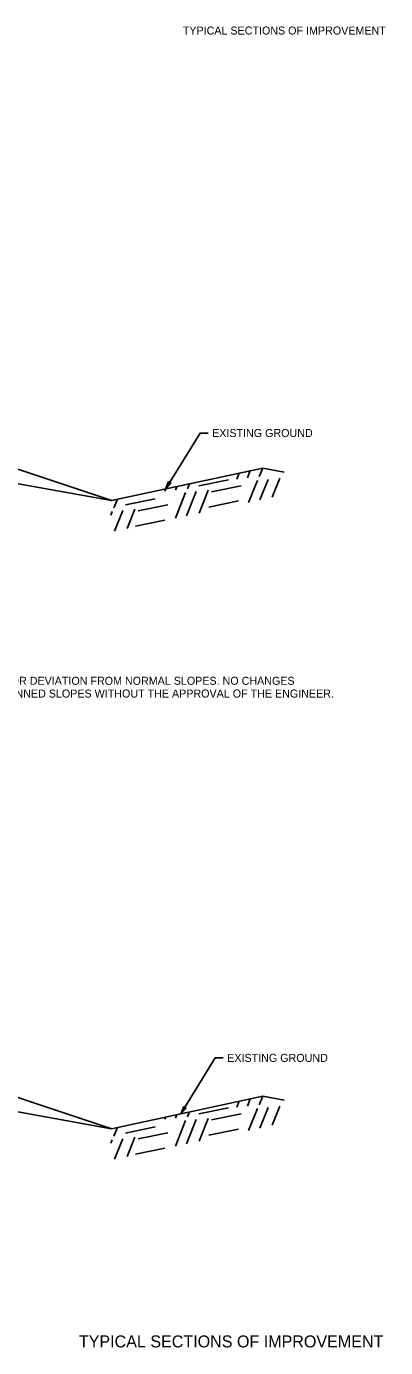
# Model space of a CAD drawing. Extents: x 1734743 to 1735935, y 759845 to 763831.
# Drawn here: x 1735803.1 to 1735830, y 759845.2 to 759944.2 of the extents above; entities that cross this region are included whole.
import ezdxf

# ---------------------------------------------------------------- set-up
doc = ezdxf.new("R2010")
doc.units = 0
for name, color, linetype in [('1', 7, 'Continuous'), ('10', 7, 'Continuous'), ('19', 7, 'Continuous'), ('20', 7, 'Continuous'), ('G-ANNO-TEXT', 7, 'Continuous')]:
    doc.layers.add(name, color=color, linetype=linetype)

msp = doc.modelspace()

# ---------------------------------------------------------------- linework, layer by layer
at = {"layer": '19'}
for p, q in [((1735809.505, 759908.711), (1735795.046, 759913.532)), ((1735820.551, 759910.501), (1735820.81, 759911.149)), ((1735816.033, 759909.813), (1735818.244, 759910.268)), ((1735818.863, 759910.323), (1735819.036, 759910.769)), ((1735819.661, 759910.409), (1735819.878, 759910.951)), ((1735819.757, 759908.573), (1735820.413, 759910.221)), ((1735820.6, 759908.755), (1735821.214, 759910.298)), ((1735821.529, 759908.963), (1735822.101, 759910.399)), ((1735813.483, 759909.415), (1735813.547, 759909.59)), ((1735814.268, 759907.394), (1735815.033, 759909.314)), ((1735814.283, 759909.491), (1735814.389, 759909.772)), ((1735815.111, 759907.576), (1735815.833, 759909.39)), ((1735815.17, 759909.593), (1735815.321, 759909.97)), ((1735816.042, 759907.774), (1735816.723, 759909.482)), ((1735816.975, 759909.368), (1735819.195, 759909.826)), ((1735809.671, 759908.162), (1735809.931, 759908.81)), ((1735810.534, 759908.381), (1735812.755, 759908.839)), ((1735811.485, 759907.939), (1735813.696, 759908.394)), ((1735816.766, 759908.224), (1735818.986, 759908.682)), ((1735809.442, 759907.626), (1735809.543, 759907.885)), ((1735809.72, 759906.416), (1735810.344, 759907.961)), ((1735810.652, 759906.614), (1735811.231, 759908.063)), ((1735811.276, 759906.795), (1735813.487, 759907.25)), ((1735809.505, 759861.629), (1735795.046, 759866.45)), ((1735818.863, 759863.24), (1735819.036, 759863.686)), ((1735819.661, 759863.326), (1735819.878, 759863.869)), ((1735820.551, 759863.418), (1735820.81, 759864.066)), ((1735814.283, 759862.409), (1735814.389, 759862.69)), ((1735815.17, 759862.511), (1735815.321, 759862.888)), ((1735816.033, 759862.73), (1735818.244, 759863.185)), ((1735816.975, 759862.285), (1735819.195, 759862.743)), ((1735819.757, 759861.49), (1735820.413, 759863.139)), ((1735820.6, 759861.673), (1735821.214, 759863.215)), ((1735821.529, 759861.88), (1735822.101, 759863.317)), ((1735809.671, 759861.079), (1735809.931, 759861.727)), ((1735810.534, 759861.299), (1735812.755, 759861.757)), ((1735813.483, 759862.333), (1735813.547, 759862.507)), ((1735814.268, 759860.311), (1735815.033, 759862.231)), ((1735815.111, 759860.494), (1735815.833, 759862.308)), ((1735816.042, 759860.692), (1735816.723, 759862.4)), ((1735809.442, 759860.544), (1735809.543, 759860.802)), ((1735809.72, 759859.333), (1735810.344, 759860.879)), ((1735810.652, 759859.531), (1735811.231, 759860.98)), ((1735811.485, 759860.857), (1735813.696, 759861.312)), ((1735816.766, 759861.142), (1735818.986, 759861.599)), ((1735811.276, 759859.713), (1735813.487, 759860.168))]:
    msp.add_line(p, q, dxfattribs=at)
for points in [[(1735737.574, 759909.405), (1735737.825, 759909.397), (1735746.995, 759910.076), (1735752.775, 759907.356), (1735767.375, 759908.375), (1735787.755, 759909.053), (1735799.985, 759910.412), (1735809.495, 759908.711), (1735820.81, 759911.149), (1735822.413, 759910.838)], [(1735738.102, 759862.335), (1735746.995, 759862.994), (1735752.775, 759860.273), (1735767.375, 759861.292), (1735787.755, 759861.971), (1735799.985, 759863.33), (1735809.495, 759861.629), (1735820.81, 759864.066), (1735822.413, 759863.755)]]:
    msp.add_lwpolyline(points, dxfattribs=at)
at = {"layer": '20'}
for p, q in [((1735813.539, 759909.574), (1735813.762, 759910.141)), ((1735813.762, 759910.141), (1735813.94, 759910.031)), ((1735813.94, 759910.031), (1735813.539, 759909.574)), ((1735813.612, 759909.715), (1735813.805, 759910.109)), ((1735813.899, 759910.053), (1735813.635, 759909.704)), ((1735814.672, 759862.736), (1735814.895, 759863.303)), ((1735815.073, 759863.193), (1735814.672, 759862.736)), ((1735814.745, 759862.877), (1735814.938, 759863.27)), ((1735815.032, 759863.214), (1735814.768, 759862.866)), ((1735814.895, 759863.303), (1735815.073, 759863.193))]:
    msp.add_line(p, q, dxfattribs=at)
for points in [[(1735816.721, 759913.773), (1735816.121, 759913.773), (1735813.539, 759909.574)], [(1735817.854, 759866.935), (1735817.254, 759866.935), (1735814.672, 759862.736)]]:
    msp.add_lwpolyline(points, dxfattribs=at)

# ---------------------------------------------------------------- texts
at = {"layer": '1'}
for s, p in [('REFER TO CROSS SECTIONS FOR DEVIATION FROM NORMAL SLOPES. NO CHANGES', (1735789.766, 759894.901)), ('SHALL BE MADE FROM THE PLANNED SLOPES WITHOUT THE APPROVAL OF THE ENGINEER.', (1735789.766, 759893.945))]:
    msp.add_text(s, height=0.6, dxfattribs=at).set_placement(p)
at = {"layer": '10'}
for p in [(1735817.021, 759913.474), (1735818.154, 759866.635)]:
    msp.add_text('EXISTING GROUND', height=0.6, dxfattribs=at).set_placement(p)
at = {"layer": 'G-ANNO-TEXT'}
for height, p in [(0.6, (1735814.827, 759943.641)), (0.9, (1735807.044, 759845.233))]:
    msp.add_text('TYPICAL SECTIONS OF IMPROVEMENT', height=height, dxfattribs=at).set_placement(p)

doc.saveas('drawing.dxf')
